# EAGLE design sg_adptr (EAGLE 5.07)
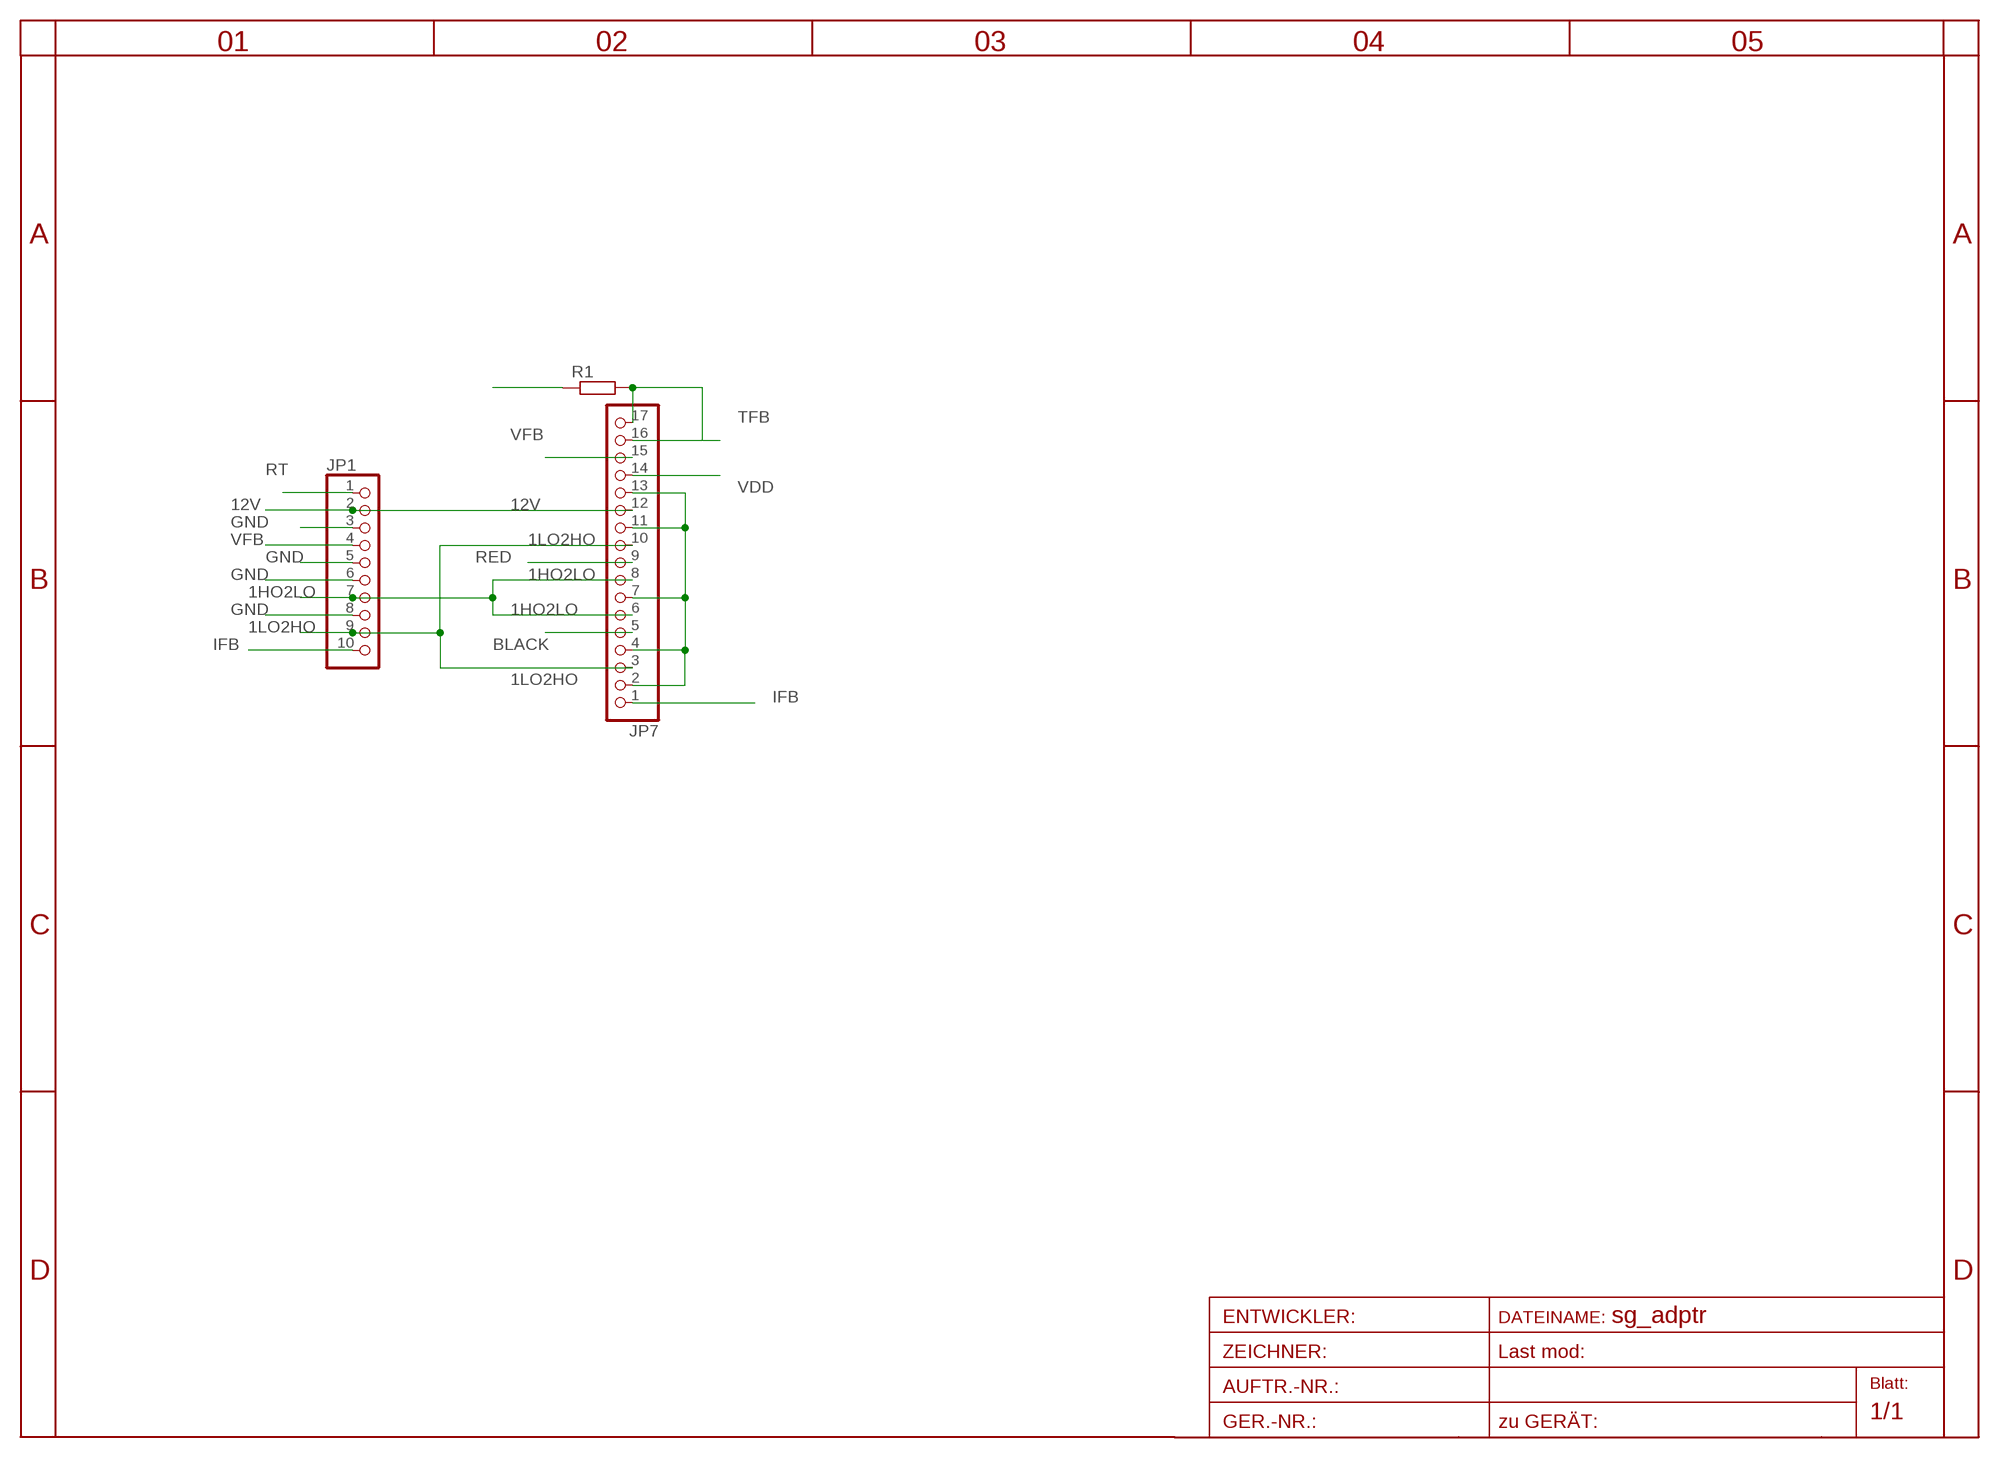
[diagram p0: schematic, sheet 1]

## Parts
JP1  PINHD-1X100X05  [1X10]
JP7  PINHD-1X17  [1X17]
R1  R-EU_0204/2V  [0204V]

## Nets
1HO2LO: JP1.7 JP7.6 JP7.8
1LO2HO: JP1.9 JP7.3 JP7.10
12V: JP1.2 JP7.12
BLACK: JP7.5
GND: JP1.3 JP1.5 JP1.6 JP1.8 JP7.2 JP7.4 JP7.7 JP7.11 JP7.13 R1.1
IFB: JP1.10 JP7.1
RED: JP7.9
RT: JP1.1
TFB: JP7.16 JP7.17 R1.2
VDD: JP7.14
VFB: JP1.4 JP7.15

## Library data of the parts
JP1 = pinhead:PINHD-1X10: PIN HEADER
JP7 = pinhead:PINHD-1X17: PIN HEADER
R1 = rcl:R-EU_: RESISTOR, European symbol

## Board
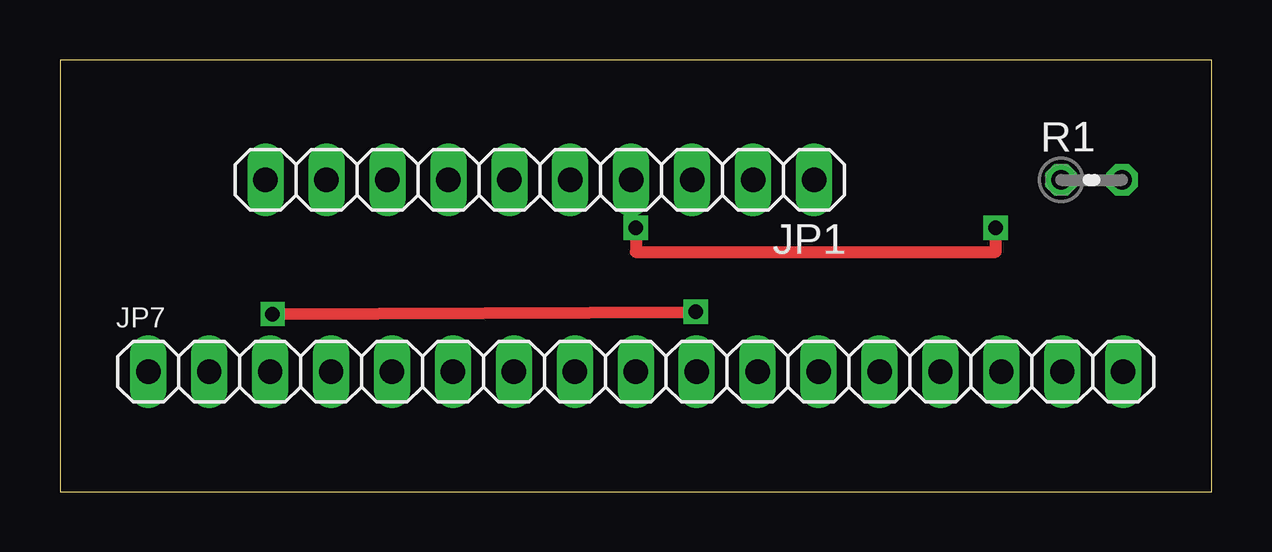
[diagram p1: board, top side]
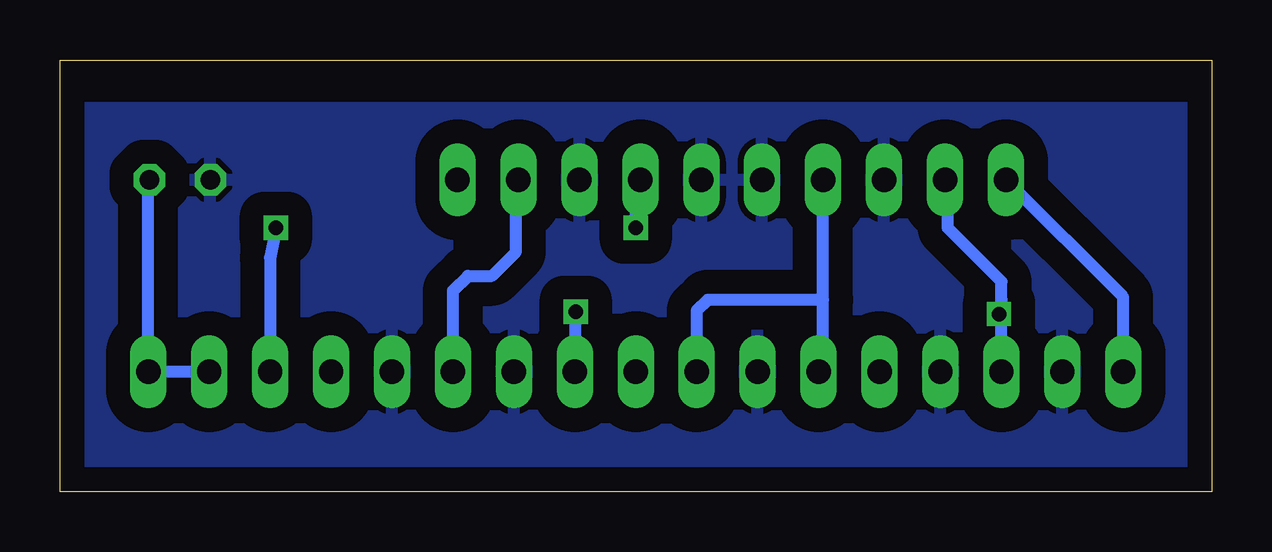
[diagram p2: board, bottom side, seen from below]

Size 48 x 18 mm. Coordinates in mm from the lower left corner, seen from the top.
Outline: 0,0 48,0 48,18 0,18 0,0
Copper layers (1*16): Top 0.035mm / dielectric 1.5mm / Bottom 0.035mm
Design rules "default *": minimum track width 10mil, minimum drill 20mil, track to track 8mil, track to pad 8mil, pad to pad 8mil, via to via 8mil, smd to smd 8mil, copper to edge 40mil, drill to drill 8mil, minimum pad ring 10mil, minimum via ring 8mil, stop-mask expansion 4mil, vias tented up to drill 0mil, thermal gap 10mil

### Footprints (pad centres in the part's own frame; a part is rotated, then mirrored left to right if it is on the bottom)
1X10 = drill 1.016 long: 1 -11.43,0; 2 -8.89,0; 3 -6.35,0; 4 -3.81,0; 5 -1.27,0; 6 1.27,0; 7 3.81,0; 8 6.35,0; 9 8.89,0; 10 11.43,0
1X17 = drill 1.016 long: 1 -20.32,0; 2 -17.78,0; 3 -15.24,0; 4 -12.7,0; 5 -10.16,0; 6 -7.62,0; 7 -5.08,0; 8 -2.54,0; 9 0,0; 10 2.54,0; 11 5.08,0; 12 7.62,0; 13 10.16,0; 14 12.7,0; 15 15.24,0; 16 17.78,0; 17 20.32,0
0204V = drill 0.813 octagon: 1 -1.27,0; 2 1.27,0

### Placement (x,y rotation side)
JP1  20,13 180 top
JP7  24,5 0 top
R1  43,13 0 top

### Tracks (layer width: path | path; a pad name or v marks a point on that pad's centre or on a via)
1HO2LO
  Bottom 0.5: 16.19,8 16.19,5.19 JP7.6 | 16.19,8 JP1.7 | JP7.8 21.46,7.54 21,8 16.19,8
1LO2HO  (via drill 0.6)
  Top 0.5: v8.86,7.4 v26.5,7.5
  Bottom 0.5: JP7.3 8.76,8 | 8.76,8 8.76,8.76 11,11 11,12.89 JP1.9 | JP7.10 26.54,7.46 v26.5,7.5 | 8.76,8 v8.86,7.4
12V
  Bottom 0.5: JP7.12 31.62,8.38 31,9 30,9 29,10 29,12.89 JP1.2
GND
  pour Bottom (isolate 1): 1,16 47,16 47,1 1,1
IFB
  Bottom 0.5: JP7.1 3.68,8.11 JP1.10
TFB
  Bottom 0.5: R1.2 44.32,12.95 JP7.17 JP7.16
VFB  (via drill 0.6)
  Top 0.5: v24,11 24,10 39,10 v39,11
  Bottom 0.5: JP1.4 24,12.81 v24,11 | v39,11 39.24,9.76 JP7.15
